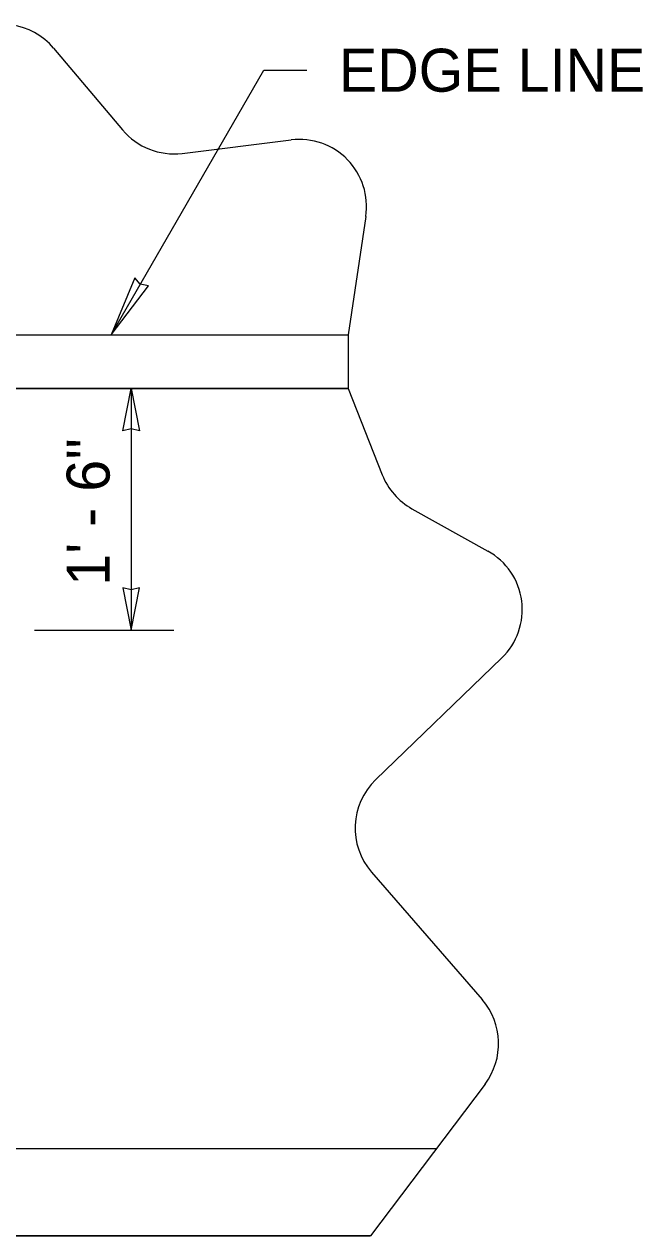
# Model space of a CAD drawing. Extents: x 99862 to 104211, y 98939 to 105076.
# Drawn here: x 102238.1 to 102468.6, y 100332.9 to 100784.1 of the extents above; entities that cross this region are included whole.
import ezdxf

# ---------------------------------------------------------------- set-up
doc = ezdxf.new("R2010")
doc.units = 0
for name, color, linetype in [('Level 15', 7, 'Continuous'), ('Level 17', 7, 'Continuous'), ('Level 20', 7, 'Continuous'), ('Level 5', 7, 'Continuous'), ('Level 50', 7, 'Continuous'), ('Level 8', 7, 'Continuous')]:
    doc.layers.add(name, color=color, linetype=linetype)

msp = doc.modelspace()

# ---------------------------------------------------------------- linework, layer by layer
at = {"layer": 'Level 15'}
for p, q in [((102270.44, 100668.46), (102327.35, 100767.02)), ((102327.35, 100767.02), (102343.35, 100767.02)), ((102277.89, 100648.46), (102277.89, 100558.46)), ((102241.89, 100558.46), (102293.89, 100558.46))]:
    msp.add_line(p, q, dxfattribs=at)
for points in [[(102270.44, 100668.46), (102284.44, 100686.74), (102281.33, 100687.32), (102279.27, 100689.72)], [(102277.9, 100648.46), (102280.98, 100632.74), (102277.9, 100633.46), (102274.81, 100632.74)], [(102277.9, 100558.46), (102280.98, 100574.19), (102277.9, 100573.46), (102274.81, 100574.19)]]:
    msp.add_lwpolyline(points, close=True, dxfattribs=at)
at = {"layer": 'Level 17'}
for p, q in [((101993.53, 100668.46), (102358.78, 100668.46)), ((101993.53, 100648.46), (102358.78, 100648.46))]:
    msp.add_line(p, q, dxfattribs=at)
msp.add_lwpolyline([(101993.53, 100668.46), (102358.78, 100668.46), (102358.78, 100648.46), (101993.53, 100648.46)], close=True, dxfattribs=at)
at = {"layer": 'Level 5'}
msp.add_lwpolyline([(101993.53, 100668.46), (102358.78, 100668.46), (102358.78, 100648.46), (101993.53, 100648.46)], close=True, dxfattribs=at)
at = {"layer": 'Level 50'}
for points in [[(102249.05, 100775.25), (102274.72, 100744.76)], [(102296.89, 100736.05), (102337.59, 100741.05)], [(102365.37, 100712.54), (102358.78, 100668.46), (102358.78, 100648.46), (102371.51, 100616.32)], [(102382.57, 100603.7), (102410.84, 100587.92)], [(102416.02, 100548.11), (102369.01, 100502.72)], [(102367.5, 100468.35), (102408.72, 100420.86)], [(102367.15, 100332.9), (102011.14, 100332.9), (101976.88, 100399.56)], [(102409.79, 100389.41), (102367.15, 100332.9)]]:
    msp.add_lwpolyline(points, dxfattribs=at)
for centre, start, end in [((102229.93, 100759.14), 40.1009, 123.3885), ((102293.85, 100760.87), 220.1009, 277.0013), ((102340.64, 100716.24), 351.499, 97.0013), ((102394.75, 100625.53), 201.6167, 240.8324), ((102398.66, 100566.1), 313.9949, 60.8324), ((102386.38, 100484.74), 133.9949, 220.9555), ((102389.84, 100404.47), 322.9618, 40.9555)]:
    msp.add_arc(centre, 25, start, end, dxfattribs=at)
at = {"layer": 'Level 8'}
for p, q in [((101994.44, 100365.4), (102391.67, 100365.4)), ((102011.14, 100332.9), (102367.15, 100332.9))]:
    msp.add_line(p, q, dxfattribs=at)

# ---------------------------------------------------------------- texts
at = {"layer": 'Level 20'}
msp.add_text('EDGE LINE', height=16, dxfattribs=at).set_placement((102355.35, 100759.02))
msp.add_text("1' - 6''", height=16, rotation=90, dxfattribs=at).set_placement((102269.9, 100575.02))

doc.saveas('drawing.dxf')
